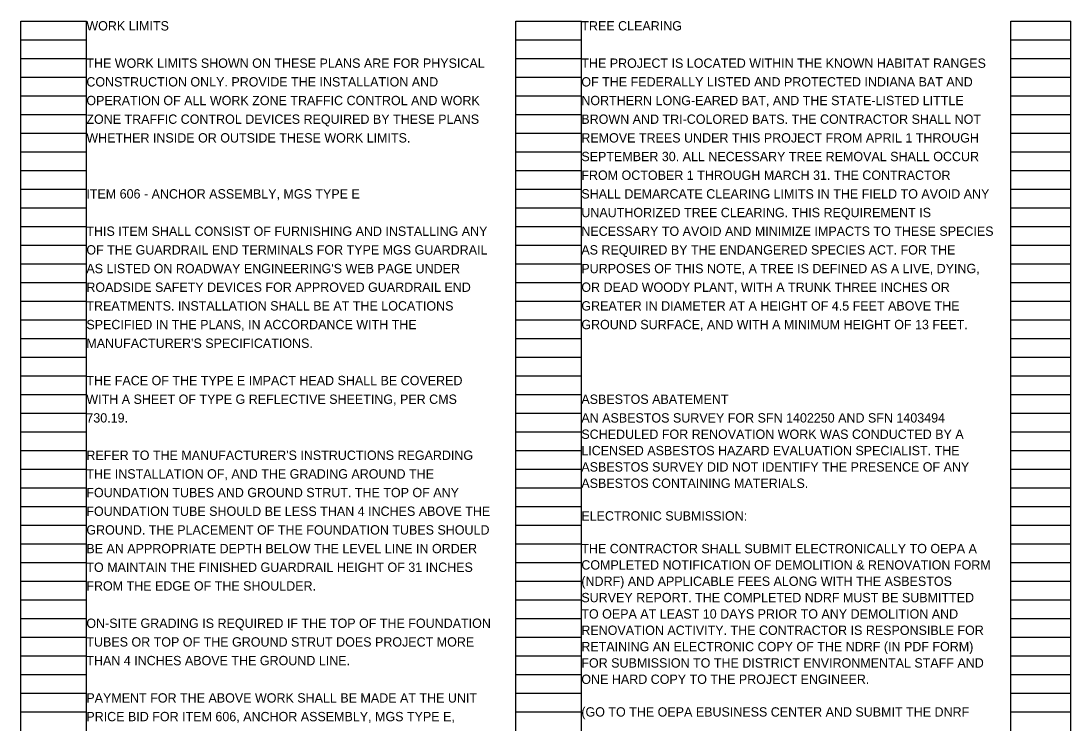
# Model space of a CAD drawing. Extents: x 0 to 78.9, y -24.2 to 22.
# Drawn here: x 61.56 to 77.3, y 10.04 to 20.57 of the extents above; entities that cross this region are included whole.
import ezdxf

# ---------------------------------------------------------------- set-up
doc = ezdxf.new("R2010")
doc.units = 0
doc.layers.add('SH_Data', color=7, linetype='Continuous')
doc.layers.add('SH_Text', color=7, linetype='Continuous')

msp = doc.modelspace()

# ---------------------------------------------------------------- linework, layer by layer
at = {"layer": 'SH_Data'}
for p, q in [((61.561, 0.407), (61.561, 20.567)), ((61.561, 20.567), (62.541, 20.567)), ((62.541, 0.407), (62.541, 20.567)), ((68.981, 0.407), (68.981, 20.567)), ((68.981, 20.567), (69.961, 20.567)), ((69.961, 0.407), (69.961, 20.567)), ((76.401, 0.407), (76.401, 20.567)), ((76.401, 20.567), (77.301, 20.567)), ((77.301, 0.407), (77.301, 20.567)), ((61.561, 20.287), (62.541, 20.287)), ((68.981, 20.287), (69.961, 20.287)), ((76.401, 20.287), (77.301, 20.287)), ((61.561, 20.007), (62.541, 20.007)), ((68.981, 20.007), (69.961, 20.007)), ((76.401, 20.007), (77.301, 20.007)), ((61.561, 19.727), (62.541, 19.727)), ((68.981, 19.727), (69.961, 19.727)), ((76.401, 19.727), (77.301, 19.727)), ((61.561, 19.447), (62.541, 19.447)), ((68.981, 19.447), (69.961, 19.447)), ((76.401, 19.447), (77.301, 19.447)), ((61.561, 19.167), (62.541, 19.167)), ((68.981, 19.167), (69.961, 19.167)), ((76.401, 19.167), (77.301, 19.167)), ((61.561, 18.887), (62.541, 18.887)), ((68.981, 18.887), (69.961, 18.887)), ((76.401, 18.887), (77.301, 18.887)), ((61.561, 18.607), (62.541, 18.607)), ((68.981, 18.607), (69.961, 18.607)), ((76.401, 18.607), (77.301, 18.607)), ((61.561, 18.327), (62.541, 18.327)), ((68.981, 18.327), (69.961, 18.327)), ((76.401, 18.327), (77.301, 18.327)), ((61.561, 18.047), (62.541, 18.047)), ((68.981, 18.047), (69.961, 18.047)), ((76.401, 18.047), (77.301, 18.047)), ((61.561, 17.767), (62.541, 17.767)), ((68.981, 17.767), (69.961, 17.767)), ((76.401, 17.767), (77.301, 17.767)), ((61.561, 17.487), (62.541, 17.487)), ((68.981, 17.487), (69.961, 17.487)), ((76.401, 17.487), (77.301, 17.487)), ((61.561, 17.207), (62.541, 17.207)), ((68.981, 17.207), (69.961, 17.207)), ((76.401, 17.207), (77.301, 17.207)), ((61.561, 16.927), (62.541, 16.927)), ((68.981, 16.927), (69.961, 16.927)), ((76.401, 16.927), (77.301, 16.927)), ((61.561, 16.647), (62.541, 16.647)), ((68.981, 16.647), (69.961, 16.647)), ((76.401, 16.647), (77.301, 16.647)), ((61.561, 16.367), (62.541, 16.367)), ((68.981, 16.367), (69.961, 16.367)), ((76.401, 16.367), (77.301, 16.367)), ((61.561, 16.087), (62.541, 16.087)), ((68.981, 16.087), (69.961, 16.087)), ((76.401, 16.087), (77.301, 16.087)), ((61.561, 15.807), (62.541, 15.807)), ((68.981, 15.807), (69.961, 15.807)), ((76.401, 15.807), (77.301, 15.807)), ((61.561, 15.527), (62.541, 15.527)), ((68.981, 15.527), (69.961, 15.527)), ((76.401, 15.527), (77.301, 15.527)), ((61.561, 15.247), (62.541, 15.247)), ((68.981, 15.247), (69.961, 15.247)), ((76.401, 15.247), (77.301, 15.247)), ((61.561, 14.967), (62.541, 14.967)), ((68.981, 14.967), (69.961, 14.967)), ((76.401, 14.967), (77.301, 14.967)), ((61.561, 14.687), (62.541, 14.687)), ((68.981, 14.687), (69.961, 14.687)), ((76.401, 14.687), (77.301, 14.687)), ((61.561, 14.407), (62.541, 14.407)), ((68.981, 14.407), (69.961, 14.407)), ((76.401, 14.407), (77.301, 14.407)), ((61.561, 14.127), (62.541, 14.127)), ((68.981, 14.127), (69.961, 14.127)), ((76.401, 14.127), (77.301, 14.127)), ((61.561, 13.847), (62.541, 13.847)), ((68.981, 13.847), (69.961, 13.847)), ((76.401, 13.847), (77.301, 13.847)), ((61.561, 13.567), (62.541, 13.567)), ((68.981, 13.567), (69.961, 13.567)), ((76.401, 13.567), (77.301, 13.567)), ((61.561, 13.287), (62.541, 13.287)), ((68.981, 13.287), (69.961, 13.287)), ((76.401, 13.287), (77.301, 13.287)), ((61.561, 13.007), (62.541, 13.007)), ((68.981, 13.007), (69.961, 13.007)), ((76.401, 13.007), (77.301, 13.007)), ((61.561, 12.727), (62.541, 12.727)), ((68.981, 12.727), (69.961, 12.727)), ((76.401, 12.727), (77.301, 12.727)), ((61.561, 12.447), (62.541, 12.447)), ((68.981, 12.447), (69.961, 12.447)), ((76.401, 12.447), (77.301, 12.447)), ((61.561, 12.167), (62.541, 12.167)), ((68.981, 12.167), (69.961, 12.167)), ((76.401, 12.167), (77.301, 12.167)), ((61.561, 11.887), (62.541, 11.887)), ((68.981, 11.887), (69.961, 11.887)), ((76.401, 11.887), (77.301, 11.887)), ((61.561, 11.607), (62.541, 11.607)), ((68.981, 11.607), (69.961, 11.607)), ((76.401, 11.607), (77.301, 11.607)), ((61.561, 11.327), (62.541, 11.327)), ((68.981, 11.327), (69.961, 11.327)), ((76.401, 11.327), (77.301, 11.327)), ((61.561, 11.047), (62.541, 11.047)), ((68.981, 11.047), (69.961, 11.047)), ((76.401, 11.047), (77.301, 11.047)), ((61.561, 10.767), (62.541, 10.767)), ((68.981, 10.767), (69.961, 10.767)), ((76.401, 10.767), (77.301, 10.767)), ((61.561, 10.487), (62.541, 10.487)), ((68.981, 10.487), (69.961, 10.487)), ((76.401, 10.487), (77.301, 10.487)), ((61.561, 10.207), (62.541, 10.207)), ((68.981, 10.207), (69.961, 10.207)), ((76.401, 10.207), (77.301, 10.207))]:
    msp.add_line(p, q, dxfattribs=at)

# ---------------------------------------------------------------- texts
at = {"layer": 'SH_Text'}
for s, p in [('WORK LIMITS', (62.541, 20.427)), ('TREE CLEARING', (69.961, 20.427)), ('THE WORK LIMITS SHOWN ON THESE PLANS ARE FOR PHYSICAL', (62.541, 19.867)), ('THE PROJECT IS LOCATED WITHIN THE KNOWN HABITAT RANGES ', (69.961, 19.867)), ('CONSTRUCTION ONLY. PROVIDE THE INSTALLATION AND', (62.541, 19.587)), ('OF THE FEDERALLY LISTED AND PROTECTED INDIANA BAT AND ', (69.961, 19.587)), ('OPERATION OF ALL WORK ZONE TRAFFIC CONTROL AND WORK', (62.541, 19.307)), ('NORTHERN LONG-EARED BAT, AND THE STATE-LISTED LITTLE ', (69.961, 19.307)), ('ZONE TRAFFIC CONTROL DEVICES REQUIRED BY THESE PLANS', (62.541, 19.027)), ('BROWN AND TRI-COLORED BATS. THE CONTRACTOR SHALL NOT ', (69.961, 19.027)), ('WHETHER INSIDE OR OUTSIDE THESE WORK LIMITS.', (62.541, 18.747)), ('REMOVE TREES UNDER THIS PROJECT FROM APRIL 1 THROUGH ', (69.961, 18.747)), ('SEPTEMBER 30. ALL NECESSARY TREE REMOVAL SHALL OCCUR ', (69.961, 18.467)), ('FROM OCTOBER 1 THROUGH MARCH 31. THE CONTRACTOR ', (69.961, 18.187)), ('ITEM 606 - ANCHOR ASSEMBLY, MGS TYPE E', (62.541, 17.907)), ('SHALL DEMARCATE CLEARING LIMITS IN THE FIELD TO AVOID ANY ', (69.961, 17.907)), ('UNAUTHORIZED TREE CLEARING. THIS REQUIREMENT IS ', (69.961, 17.627)), ('THIS ITEM SHALL CONSIST OF FURNISHING AND INSTALLING ANY', (62.541, 17.347)), ('NECESSARY TO AVOID AND MINIMIZE IMPACTS TO THESE SPECIES ', (69.961, 17.347)), ('OF THE GUARDRAIL END TERMINALS FOR TYPE MGS GUARDRAIL', (62.541, 17.067)), ('AS REQUIRED BY THE ENDANGERED SPECIES ACT. FOR THE ', (69.961, 17.067)), ("AS LISTED ON ROADWAY ENGINEERING'S WEB PAGE UNDER", (62.541, 16.787)), ('PURPOSES OF THIS NOTE, A TREE IS DEFINED AS A LIVE, DYING, ', (69.961, 16.787)), ('ROADSIDE SAFETY DEVICES FOR APPROVED GUARDRAIL END', (62.541, 16.507)), ('OR DEAD WOODY PLANT, WITH A TRUNK THREE INCHES OR ', (69.961, 16.507)), ('TREATMENTS. INSTALLATION SHALL BE AT THE LOCATIONS', (62.541, 16.227)), ('GREATER IN DIAMETER AT A HEIGHT OF 4.5 FEET ABOVE THE ', (69.961, 16.227)), ('SPECIFIED IN THE PLANS, IN ACCORDANCE WITH THE', (62.541, 15.947)), ('GROUND SURFACE, AND WITH A MINIMUM HEIGHT OF 13 FEET.', (69.961, 15.947)), ("MANUFACTURER'S SPECIFICATIONS.", (62.541, 15.667)), ('THE FACE OF THE TYPE E IMPACT HEAD SHALL BE COVERED', (62.541, 15.107)), ('WITH A SHEET OF TYPE G REFLECTIVE SHEETING, PER CMS', (62.541, 14.827)), ('ASBESTOS ABATEMENT', (69.961, 14.827)), ('730.19.', (62.541, 14.547)), ('AN ASBESTOS SURVEY FOR SFN 1402250 AND SFN 1403494 ', (69.961, 14.547)), ('SCHEDULED FOR RENOVATION WORK WAS CONDUCTED BY A ', (69.961, 14.302)), ('LICENSED ASBESTOS HAZARD EVALUATION SPECIALIST. THE ', (69.961, 14.057)), ("REFER TO THE MANUFACTURER'S INSTRUCTIONS REGARDING", (62.541, 13.987)), ('ASBESTOS SURVEY DID NOT IDENTIFY THE PRESENCE OF ANY ', (69.961, 13.812)), ('THE INSTALLATION OF, AND THE GRADING AROUND THE', (62.541, 13.707)), ('ASBESTOS CONTAINING MATERIALS.', (69.961, 13.567)), ('FOUNDATION TUBES AND GROUND STRUT. THE TOP OF ANY', (62.541, 13.427)), ('FOUNDATION TUBE SHOULD BE LESS THAN 4 INCHES ABOVE THE', (62.541, 13.147)), ('ELECTRONIC SUBMISSION:', (69.961, 13.077)), ('GROUND. THE PLACEMENT OF THE FOUNDATION TUBES SHOULD', (62.541, 12.867)), ('BE AN APPROPRIATE DEPTH BELOW THE LEVEL LINE IN ORDER', (62.541, 12.587)), ('THE CONTRACTOR SHALL SUBMIT ELECTRONICALLY TO OEPA A ', (69.961, 12.587)), ('TO MAINTAIN THE FINISHED GUARDRAIL HEIGHT OF 31 INCHES', (62.541, 12.307)), ('COMPLETED NOTIFICATION OF DEMOLITION & RENOVATION FORM ', (69.961, 12.342)), ('FROM THE EDGE OF THE SHOULDER.', (62.541, 12.027)), ('(NDRF) AND APPLICABLE FEES ALONG WITH THE ASBESTOS ', (69.961, 12.097)), ('SURVEY REPORT. THE COMPLETED NDRF MUST BE SUBMITTED ', (69.961, 11.852)), ('TO OEPA AT LEAST 10 DAYS PRIOR TO ANY DEMOLITION AND ', (69.961, 11.607)), ('ON-SITE GRADING IS REQUIRED IF THE TOP OF THE FOUNDATION', (62.541, 11.467)), ('RENOVATION ACTIVITY. THE CONTRACTOR IS RESPONSIBLE FOR ', (69.961, 11.362)), ('TUBES OR TOP OF THE GROUND STRUT DOES PROJECT MORE', (62.541, 11.187)), ('RETAINING AN ELECTRONIC COPY OF THE NDRF (IN PDF FORM) ', (69.961, 11.117)), ('THAN 4 INCHES ABOVE THE GROUND LINE.', (62.541, 10.907)), ('FOR SUBMISSION TO THE DISTRICT ENVIRONMENTAL STAFF AND ', (69.961, 10.872)), ('ONE HARD COPY TO THE PROJECT ENGINEER.', (69.961, 10.627)), ('PAYMENT FOR THE ABOVE WORK SHALL BE MADE AT THE UNIT', (62.541, 10.347)), ('(GO TO THE OEPA EBUSINESS CENTER AND SUBMIT THE DNRF ', (69.961, 10.137)), ('PRICE BID FOR ITEM 606, ANCHOR ASSEMBLY, MGS TYPE E,', (62.541, 10.067))]:
    msp.add_text(s, height=0.14, dxfattribs=at).set_placement(p)

doc.saveas('drawing.dxf')
